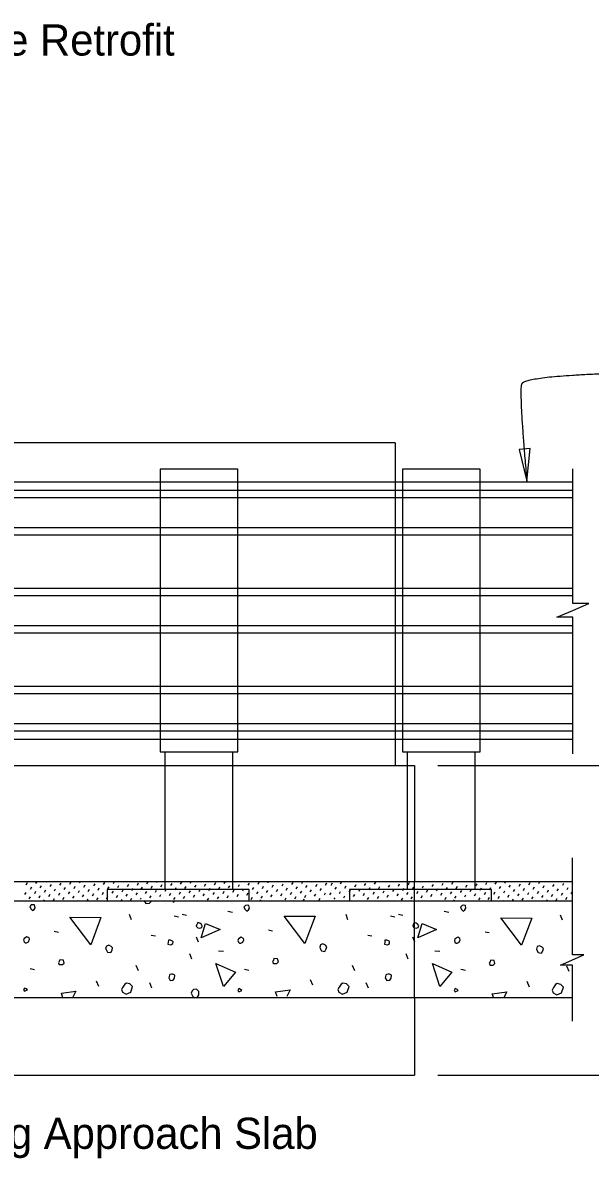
# Model space of a CAD drawing. Extents: x 1.5 to 68.7, y 0 to 31.1.
# Drawn here: x 34.15 to 37.81, y 9.2 to 16.53 of the extents above; entities that cross this region are included whole.
import ezdxf

# ---------------------------------------------------------------- set-up
doc = ezdxf.new("R2010")
doc.units = 0
for name, color, linetype in [('Dimension', 7, 'Continuous'), ('Miscellaneous', 7, 'Continuous'), ('TextStructures', 7, 'Continuous'), ('TrafBarrierConc', 7, 'Continuous')]:
    doc.layers.add(name, color=color, linetype=linetype)

msp = doc.modelspace()

# ---------------------------------------------------------------- linework, layer by layer
at = {"layer": 'Dimension'}
for p, q in [((36.8263, 11.7345), (39.8006, 11.7345)), ((36.8263, 9.7345), (39.8006, 9.7345))]:
    msp.add_line(p, q, dxfattribs=at)
msp.add_lwpolyline([(37.4003, 13.5697), (37.4212, 13.7799), (37.3508, 13.775)], close=True, dxfattribs=at)
for points in [[(37.6978, 11.8101), (37.6978, 12.6907), (37.5945, 12.6907), (37.6978, 12.7357), (37.8012, 12.7807), (37.6978, 12.7807), (37.6978, 13.649)], [(37.6953, 10.0834), (37.6953, 10.4448), (37.6178, 10.4448), (37.7678, 10.5111), (37.6953, 10.5111), (37.6953, 11.1369)]]:
    msp.add_lwpolyline(points, dxfattribs=at)
msp.add_open_spline([(37.8896, 14.2621), (37.3828, 14.2426), (37.3496, 14.1481), (37.4003, 13.5697)], degree=2, dxfattribs=at)
at = {"layer": 'Miscellaneous'}
for p, q in [((28.9195, 13.5645), (37.6978, 13.5645)), ((29.5771, 13.5123), (37.6978, 13.5123)), ((29.5783, 13.4641), (37.6978, 13.4641)), ((29.5831, 13.2713), (37.6978, 13.2713)), ((29.5842, 13.2231), (37.6978, 13.2231)), ((29.5807, 12.8791), (37.6978, 12.8791)), ((29.5795, 12.8309), (37.6978, 12.8309)), ((29.5747, 12.6381), (37.6978, 12.6381)), ((29.5735, 12.5899), (37.6978, 12.5899)), ((29.5831, 12.1978), (37.6978, 12.1978)), ((29.5842, 12.246), (37.6978, 12.246)), ((29.5771, 11.9567), (37.6978, 11.9567)), ((29.5783, 12.0049), (37.6978, 12.0049)), ((28.9195, 11.9044), (37.6978, 11.9044)), ((35.0654, 10.9324), (35.0654, 11.8211)), ((35.5029, 10.9324), (35.5029, 11.8211)), ((36.6296, 10.9324), (36.6296, 11.8211)), ((37.0671, 10.9324), (37.0671, 11.8211)), ((34.1686, 10.9633), (34.1767, 10.9773)), ((34.1963, 10.9356), (34.2044, 10.9496)), ((34.2321, 10.9714), (34.2397, 10.9845)), ((34.2598, 10.9437), (34.2679, 10.9577)), ((34.2875, 10.916), (34.2956, 10.93)), ((34.2956, 10.9795), (34.2985, 10.9845)), ((34.3233, 10.9518), (34.3314, 10.9658)), ((34.351, 10.9241), (34.3591, 10.9381)), ((34.3868, 10.9599), (34.3949, 10.9739)), ((34.4145, 10.9322), (34.4226, 10.9462)), ((34.4503, 10.968), (34.4584, 10.982)), ((34.478, 10.9403), (34.4861, 10.9543)), ((34.5057, 10.9126), (34.5138, 10.9266)), ((34.5138, 10.9761), (34.5186, 10.9845)), ((34.5415, 10.9484), (34.5496, 10.9624)), ((34.5692, 10.9207), (34.5773, 10.9347)), ((34.5773, 10.9842), (34.5774, 10.9845)), ((34.605, 10.9565), (34.6131, 10.9705)), ((34.6327, 10.9288), (34.6408, 10.9428)), ((34.6685, 10.9646), (34.6766, 10.9786)), ((34.6962, 10.9369), (34.7043, 10.9509)), ((34.732, 10.9727), (34.7388, 10.9845)), ((34.7597, 10.9451), (34.7678, 10.959)), ((34.7874, 10.9174), (34.7955, 10.9314)), ((34.7955, 10.9808), (34.7976, 10.9845)), ((34.8232, 10.9532), (34.8313, 10.9671)), ((34.8509, 10.9255), (34.859, 10.9395)), ((34.8867, 10.9613), (34.8948, 10.9753)), ((34.9118, 10.9343), (34.9199, 10.9483)), ((34.9476, 10.9701), (34.9557, 10.9841)), ((34.9753, 10.9424), (34.9834, 10.9564)), ((35.003, 10.9147), (35.0111, 10.9287)), ((35.0111, 10.9782), (35.0147, 10.9845)), ((35.0388, 10.9505), (35.0469, 10.9645)), ((35.0664, 10.9228), (35.0745, 10.9368)), ((35.1022, 10.9586), (35.1103, 10.9726)), ((35.1299, 10.9309), (35.138, 10.9449)), ((35.1657, 10.9667), (35.1738, 10.9807)), ((35.1934, 10.939), (35.2015, 10.953)), ((35.2292, 10.9748), (35.2348, 10.9845)), ((35.2569, 10.9471), (35.265, 10.9611)), ((35.2846, 10.9194), (35.2927, 10.9334)), ((35.2927, 10.9829), (35.2936, 10.9845)), ((35.3204, 10.9552), (35.3285, 10.9692)), ((35.3481, 10.9275), (35.3562, 10.9415)), ((35.3839, 10.9633), (35.392, 10.9773)), ((35.4116, 10.9356), (35.4197, 10.9496)), ((35.4474, 10.9714), (35.455, 10.9845)), ((35.4751, 10.9437), (35.4832, 10.9577)), ((35.5028, 10.916), (35.5109, 10.93)), ((35.5109, 10.9795), (35.5138, 10.9845)), ((35.5386, 10.9518), (35.5467, 10.9658)), ((35.5663, 10.9241), (35.5744, 10.9381)), ((35.6021, 10.9599), (35.6102, 10.9739)), ((35.6298, 10.9322), (35.6379, 10.9462)), ((35.6656, 10.968), (35.6737, 10.982)), ((35.6933, 10.9403), (35.7014, 10.9543)), ((35.721, 10.9126), (35.7291, 10.9266)), ((35.7291, 10.9761), (35.7339, 10.9845)), ((35.7568, 10.9484), (35.7649, 10.9624)), ((35.7845, 10.9207), (35.7926, 10.9347)), ((35.7926, 10.9842), (35.7927, 10.9845)), ((35.8203, 10.9565), (35.8284, 10.9705)), ((35.8479, 10.9288), (35.856, 10.9428)), ((35.8837, 10.9646), (35.8918, 10.9786)), ((35.9114, 10.9369), (35.9195, 10.9509)), ((35.9472, 10.9727), (35.954, 10.9845)), ((35.9749, 10.9451), (35.983, 10.959)), ((36.0026, 10.9174), (36.0107, 10.9314)), ((36.0107, 10.9808), (36.0128, 10.9845)), ((36.0384, 10.9532), (36.0465, 10.9671)), ((36.0661, 10.9255), (36.0742, 10.9395)), ((36.1019, 10.9613), (36.11, 10.9753)), ((36.1377, 10.9613), (36.1458, 10.9753)), ((36.1628, 10.9343), (36.1709, 10.9483)), ((36.1986, 10.9701), (36.2067, 10.9841)), ((36.2263, 10.9424), (36.2344, 10.9564)), ((36.254, 10.9147), (36.2621, 10.9287)), ((36.2898, 10.9505), (36.2979, 10.9645)), ((36.3175, 10.9228), (36.3256, 10.9368)), ((36.3533, 10.9586), (36.3614, 10.9726)), ((36.381, 10.9309), (36.3891, 10.9449)), ((36.4168, 10.9667), (36.4249, 10.9807)), ((36.4444, 10.939), (36.4526, 10.953)), ((36.5079, 10.9471), (36.516, 10.9611)), ((36.5356, 10.9194), (36.5437, 10.9334)), ((36.5714, 10.9552), (36.5795, 10.9692)), ((36.5991, 10.9275), (36.6072, 10.9415)), ((36.6349, 10.9633), (36.643, 10.9773)), ((36.6626, 10.9356), (36.6707, 10.9496)), ((36.7261, 10.9437), (36.7342, 10.9577)), ((36.7538, 10.916), (36.7619, 10.93)), ((36.7896, 10.9518), (36.7977, 10.9658)), ((36.8173, 10.9241), (36.8254, 10.9381)), ((36.8531, 10.9599), (36.8612, 10.9739)), ((36.8808, 10.9322), (36.8889, 10.9462)), ((36.9166, 10.968), (36.9247, 10.982)), ((36.9443, 10.9403), (36.9524, 10.9543)), ((36.972, 10.9126), (36.9801, 10.9266)), ((37.0078, 10.9484), (37.0159, 10.9624)), ((37.0355, 10.9207), (37.0436, 10.9347)), ((37.0713, 10.9565), (37.0794, 10.9705)), ((37.099, 10.9288), (37.1071, 10.9428)), ((37.1348, 10.9646), (37.1429, 10.9786)), ((37.16, 10.931), (37.1681, 10.945)), ((37.1958, 10.9668), (37.2039, 10.9808)), ((37.2235, 10.9391), (37.2316, 10.9531)), ((37.2593, 10.9749), (37.2649, 10.9845)), ((37.287, 10.9472), (37.2951, 10.9612)), ((37.3147, 10.9195), (37.3228, 10.9335)), ((37.3228, 10.983), (37.3237, 10.9845)), ((37.3505, 10.9553), (37.3586, 10.9693)), ((37.3782, 10.9276), (37.3863, 10.9416)), ((37.414, 10.9634), (37.4221, 10.9774)), ((37.4417, 10.9357), (37.4498, 10.9497)), ((37.4775, 10.9715), (37.485, 10.9845)), ((37.5052, 10.9438), (37.5133, 10.9578)), ((37.5329, 10.9161), (37.541, 10.9301)), ((37.541, 10.9796), (37.5438, 10.9845)), ((37.5687, 10.9519), (37.5768, 10.9659)), ((37.5964, 10.9242), (37.6045, 10.9382)), ((37.6322, 10.96), (37.6403, 10.974)), ((37.6599, 10.9323), (37.668, 10.9463)), ((37.6956, 10.9681), (37.6978, 10.9718)), ((34.1605, 10.8998), (34.1686, 10.9138)), ((34.1882, 10.8721), (34.1963, 10.8861)), ((34.224, 10.9079), (34.2321, 10.9219)), ((34.2517, 10.8802), (34.2598, 10.8942)), ((34.2834, 10.8595), (34.2875, 10.8665)), ((34.3152, 10.8883), (34.3233, 10.9023)), ((34.3429, 10.8606), (34.351, 10.8746)), ((34.3787, 10.8964), (34.3868, 10.9104)), ((34.4064, 10.8687), (34.4145, 10.8827)), ((34.4422, 10.9045), (34.4503, 10.9185)), ((34.4699, 10.8768), (34.478, 10.8908)), ((34.5036, 10.8595), (34.5057, 10.8631)), ((34.5334, 10.8849), (34.5415, 10.8989)), ((34.5624, 10.8595), (34.5692, 10.8712)), ((34.5969, 10.893), (34.605, 10.907)), ((34.6246, 10.8654), (34.6327, 10.8793)), ((34.6604, 10.9012), (34.6685, 10.9151)), ((34.6881, 10.8735), (34.6962, 10.8875)), ((34.7237, 10.8595), (34.7239, 10.8598)), ((34.7239, 10.9093), (34.732, 10.9232)), ((34.7516, 10.8816), (34.7597, 10.8956)), ((34.7825, 10.8595), (34.7874, 10.8679)), ((34.8151, 10.8897), (34.8232, 10.9037)), ((34.8428, 10.862), (34.8509, 10.876)), ((34.8786, 10.8978), (34.8867, 10.9118)), ((34.9062, 10.8701), (34.9113, 10.8788)), ((34.9395, 10.9066), (34.9476, 10.9206)), ((34.9672, 10.8789), (34.9753, 10.8929)), ((35.0306, 10.887), (35.0388, 10.901)), ((35.0941, 10.8951), (35.1022, 10.9091)), ((35.1218, 10.8674), (35.1299, 10.8814)), ((35.1576, 10.9032), (35.1657, 10.9172)), ((35.1853, 10.8755), (35.1934, 10.8895)), ((35.2211, 10.9113), (35.2292, 10.9253)), ((35.2488, 10.8836), (35.2569, 10.8976)), ((35.3123, 10.8917), (35.3204, 10.9057)), ((35.34, 10.864), (35.3481, 10.878)), ((35.3758, 10.8998), (35.3839, 10.9138)), ((35.3996, 10.8595), (35.4009, 10.8618)), ((35.4035, 10.8721), (35.4116, 10.8861)), ((35.4393, 10.9079), (35.4474, 10.9219)), ((35.467, 10.8802), (35.4751, 10.8942)), ((35.5305, 10.8883), (35.5386, 10.9023)), ((35.594, 10.8964), (35.6021, 10.9104)), ((35.6217, 10.8687), (35.6298, 10.8827)), ((35.6575, 10.9045), (35.6656, 10.9185)), ((35.6785, 10.8595), (35.6826, 10.8665)), ((35.6852, 10.8768), (35.6933, 10.8908)), ((35.7487, 10.8849), (35.7568, 10.8989)), ((35.8121, 10.893), (35.8203, 10.907)), ((35.8398, 10.8654), (35.8479, 10.8793)), ((35.8756, 10.9012), (35.8837, 10.9151)), ((35.8986, 10.8595), (35.9008, 10.8631)), ((35.9033, 10.8735), (35.9114, 10.8875)), ((35.9391, 10.9093), (35.9472, 10.9232)), ((35.9574, 10.8595), (35.9643, 10.8712)), ((35.9668, 10.8816), (35.9749, 10.8956)), ((36.0303, 10.8897), (36.0384, 10.9037)), ((36.058, 10.862), (36.0661, 10.876)), ((36.0938, 10.8978), (36.1019, 10.9118)), ((36.1296, 10.8978), (36.1377, 10.9118)), ((36.1573, 10.8701), (36.1623, 10.8788)), ((36.1905, 10.9066), (36.1986, 10.9206)), ((36.2182, 10.8789), (36.2263, 10.8929)), ((36.2817, 10.887), (36.2898, 10.901)), ((36.3452, 10.8951), (36.3533, 10.9091)), ((36.3729, 10.8674), (36.381, 10.8814)), ((36.4087, 10.9032), (36.4168, 10.9172)), ((36.4363, 10.8755), (36.4444, 10.8895)), ((36.4721, 10.9113), (36.4802, 10.9253)), ((36.4998, 10.8836), (36.5079, 10.8976)), ((36.5633, 10.8917), (36.5714, 10.9057)), ((36.591, 10.864), (36.5991, 10.878)), ((36.6268, 10.8998), (36.6349, 10.9138)), ((36.6506, 10.8595), (36.6519, 10.8618)), ((36.6545, 10.8721), (36.6626, 10.8861)), ((36.6903, 10.9079), (36.6984, 10.9219)), ((36.718, 10.8802), (36.7261, 10.8942)), ((36.7815, 10.8883), (36.7896, 10.9023)), ((36.845, 10.8964), (36.8531, 10.9104)), ((36.8727, 10.8687), (36.8808, 10.8827)), ((36.9085, 10.9045), (36.9166, 10.9185)), ((36.9295, 10.8595), (36.9336, 10.8665)), ((36.9362, 10.8768), (36.9443, 10.8908)), ((36.9997, 10.8849), (37.0078, 10.8989)), ((37.0632, 10.893), (37.0713, 10.907)), ((37.0909, 10.8654), (37.099, 10.8793)), ((37.1267, 10.9012), (37.1348, 10.9151)), ((37.1519, 10.8675), (37.16, 10.8815)), ((37.1877, 10.9033), (37.1958, 10.9173)), ((37.2154, 10.8756), (37.2235, 10.8896)), ((37.2499, 10.8595), (37.2512, 10.8619)), ((37.2512, 10.9114), (37.2593, 10.9254)), ((37.2789, 10.8837), (37.287, 10.8977)), ((37.3087, 10.8595), (37.3147, 10.87)), ((37.3424, 10.8918), (37.3505, 10.9058)), ((37.3701, 10.8641), (37.3782, 10.8781)), ((37.4059, 10.8999), (37.414, 10.9139)), ((37.4336, 10.8722), (37.4417, 10.8862)), ((37.4694, 10.908), (37.4775, 10.922)), ((37.4971, 10.8803), (37.5052, 10.8943)), ((37.5044, 10.8561), (37.5045, 10.8563)), ((37.5288, 10.8595), (37.5329, 10.8666)), ((37.5606, 10.8884), (37.5687, 10.9024)), ((37.5883, 10.8607), (37.5964, 10.8747)), ((37.6241, 10.8965), (37.6322, 10.9105)), ((37.6517, 10.8688), (37.6599, 10.8828)), ((37.6875, 10.9046), (37.6956, 10.9186)), ((35.4704, 10.7923), (35.5004, 10.787)), ((36.8675, 10.7923), (36.8975, 10.787)), ((34.849, 10.7375), (34.8366, 10.7711)), ((35.123, 10.764), (35.1513, 10.757)), ((35.1747, 10.7733), (35.203, 10.7662)), ((36.2461, 10.7375), (36.2337, 10.7711)), ((36.5201, 10.764), (36.5484, 10.757)), ((36.5718, 10.7733), (36.6001, 10.7662)), ((37.6297, 10.7341), (37.6173, 10.7677)), ((34.3505, 10.6633), (34.377, 10.658)), ((34.9763, 10.6385), (35.0028, 10.6332)), ((35.7329, 10.6715), (35.7594, 10.6662)), ((36.3734, 10.6385), (36.3999, 10.6332)), ((37.1312, 10.6598), (37.1577, 10.6545)), ((35.2808, 10.5921), (35.2684, 10.6257)), ((36.6779, 10.5921), (36.6655, 10.6257)), ((35.2384, 10.4825), (35.2242, 10.5179)), ((35.4103, 10.5378), (35.4421, 10.5342)), ((36.6355, 10.4825), (36.6213, 10.5179)), ((36.8074, 10.5378), (36.8392, 10.5342)), ((34.1949, 10.4229), (34.2232, 10.4158)), ((34.8932, 10.4069), (34.8791, 10.4423)), ((35.5782, 10.4193), (35.6065, 10.4122)), ((36.2903, 10.4069), (36.2762, 10.4423)), ((36.9753, 10.4193), (37.0036, 10.4122)), ((37.6739, 10.4035), (37.6597, 10.4389)), ((34.6369, 10.3062), (34.6227, 10.3415)), ((36.0192, 10.3144), (36.0051, 10.3497)), ((34.9803, 10.2951), (34.9661, 10.3305)), ((36.3774, 10.2951), (36.3632, 10.3305)), ((37.4176, 10.3027), (37.4034, 10.3381))]:
    msp.add_line(p, q, dxfattribs=at)
for points in [[(35.0342, 11.8211), (35.5342, 11.8211), (35.5342, 13.6478), (35.0342, 13.6478)], [(36.5984, 11.8211), (37.0984, 11.8211), (37.0984, 13.6478), (36.5984, 13.6478)], [(34.6907, 10.8595), (35.6073, 10.8595), (35.6073, 10.9324), (34.6907, 10.9324)], [(36.255, 10.8595), (37.1716, 10.8595), (37.1716, 10.9324), (36.255, 10.9324)]]:
    msp.add_lwpolyline(points, close=True, dxfattribs=at)
for points in [[(34.9311, 10.8594), (34.9409, 10.8436), (34.9639, 10.8453), (34.9728, 10.8542), (34.978, 10.8594)], [(35.1199, 10.8493), (35.1167, 10.8594)], [(35.1251, 10.8594), (35.1199, 10.8493)], [(34.1985, 10.8082), (34.2091, 10.7976), (34.2197, 10.8047), (34.2268, 10.8153), (34.2232, 10.833), (34.2144, 10.8347), (34.202, 10.833), (34.1914, 10.8224), (34.1985, 10.8082)], [(35.5818, 10.8047), (35.5924, 10.7941), (35.603, 10.8012), (35.61, 10.8118), (35.6065, 10.8294), (35.5977, 10.8312), (35.5853, 10.8294), (35.5747, 10.8188), (35.5818, 10.8047)], [(36.9788, 10.8047), (36.9894, 10.7941), (37.0001, 10.8012), (37.0071, 10.8118), (37.0036, 10.8294), (36.9948, 10.8312), (36.9824, 10.8294), (36.9718, 10.8188), (36.9788, 10.8047)], [(34.5856, 10.5766), (34.4513, 10.7534), (34.651, 10.7517), (34.5856, 10.5766)], [(35.2773, 10.6849), (35.2896, 10.6832), (35.302, 10.6885), (35.3055, 10.6991), (35.3002, 10.7079), (35.2896, 10.715), (35.2773, 10.7203), (35.2702, 10.7061), (35.2667, 10.6955), (35.2773, 10.6849)], [(35.2989, 10.6208), (35.3272, 10.7128), (35.4209, 10.6756), (35.2989, 10.6208)], [(35.968, 10.5849), (35.8336, 10.7616), (36.0334, 10.7599), (35.968, 10.5849)], [(36.6743, 10.6849), (36.6867, 10.6832), (36.6991, 10.6885), (36.7026, 10.6991), (36.6973, 10.7079), (36.6867, 10.715), (36.6743, 10.7203), (36.6673, 10.7061), (36.6637, 10.6955), (36.6743, 10.6849)], [(36.696, 10.6208), (36.7243, 10.7128), (36.818, 10.6756), (36.696, 10.6208)], [(37.3663, 10.5732), (37.2319, 10.75), (37.4317, 10.7482), (37.3663, 10.5732)], [(34.1631, 10.589), (34.1702, 10.589), (34.1843, 10.5961), (34.1896, 10.612), (34.1879, 10.6208), (34.1737, 10.6279), (34.1561, 10.6173), (34.1525, 10.6067), (34.1561, 10.5961), (34.1631, 10.589)], [(34.6846, 10.5448), (34.6935, 10.5289), (34.7147, 10.5254), (34.7235, 10.5413), (34.727, 10.5554), (34.7182, 10.5643), (34.7023, 10.5731), (34.6864, 10.5678), (34.6811, 10.5519), (34.6846, 10.5448)], [(35.0841, 10.5802), (35.1036, 10.5749), (35.116, 10.5837), (35.1177, 10.5961), (35.1142, 10.5996), (35.1, 10.6067), (35.0877, 10.6049), (35.0859, 10.5926), (35.0841, 10.5802)], [(35.5464, 10.5855), (35.5535, 10.5855), (35.5676, 10.5926), (35.5729, 10.6085), (35.5712, 10.6173), (35.557, 10.6244), (35.5393, 10.6138), (35.5358, 10.6032), (35.5393, 10.5926), (35.5464, 10.5855)], [(36.067, 10.553), (36.0758, 10.5371), (36.097, 10.5336), (36.1059, 10.5495), (36.1094, 10.5636), (36.1006, 10.5725), (36.0847, 10.5813), (36.0687, 10.576), (36.0634, 10.5601), (36.067, 10.553)], [(36.4812, 10.5802), (36.5007, 10.5749), (36.513, 10.5837), (36.5148, 10.5961), (36.5113, 10.5996), (36.4971, 10.6067), (36.4848, 10.6049), (36.483, 10.5926), (36.4812, 10.5802)], [(36.9435, 10.5855), (36.9506, 10.5855), (36.9647, 10.5926), (36.97, 10.6085), (36.9682, 10.6173), (36.9541, 10.6244), (36.9364, 10.6138), (36.9329, 10.6032), (36.9364, 10.5926), (36.9435, 10.5855)], [(37.4653, 10.5414), (37.4741, 10.5255), (37.4953, 10.5219), (37.5042, 10.5379), (37.5077, 10.552), (37.4989, 10.5608), (37.483, 10.5697), (37.4671, 10.5644), (37.4618, 10.5485), (37.4653, 10.5414)], [(35.7647, 10.4558), (35.7859, 10.4558), (35.7965, 10.4664), (35.7912, 10.4859), (35.7682, 10.4876), (35.7647, 10.477), (35.7594, 10.4682), (35.7647, 10.4558), (35.7612, 10.4593)], [(34.3823, 10.4476), (34.4035, 10.4476), (34.4141, 10.4582), (34.4088, 10.4777), (34.3859, 10.4794), (34.3823, 10.4688), (34.377, 10.46), (34.3823, 10.4476), (34.3788, 10.4511)], [(35.4417, 10.3075), (35.3939, 10.4542), (35.5194, 10.3994), (35.4417, 10.3075)], [(36.8387, 10.3075), (36.791, 10.4542), (36.9165, 10.3994), (36.8387, 10.3075)], [(37.163, 10.4442), (37.1842, 10.4442), (37.1948, 10.4548), (37.1895, 10.4742), (37.1665, 10.476), (37.163, 10.4654), (37.1577, 10.4565), (37.163, 10.4442), (37.1595, 10.4477)], [(35.0899, 10.3623), (35.0987, 10.3464), (35.1182, 10.3482), (35.127, 10.3605), (35.1288, 10.38), (35.1164, 10.3853), (35.1076, 10.3871), (35.0969, 10.3835), (35.0934, 10.38), (35.0899, 10.3623)], [(36.487, 10.3623), (36.4958, 10.3464), (36.5152, 10.3482), (36.5241, 10.3605), (36.5259, 10.38), (36.5135, 10.3853), (36.5046, 10.3871), (36.494, 10.3835), (36.4905, 10.38), (36.487, 10.3623)], [(34.1574, 10.2757), (34.1768, 10.2845), (34.1698, 10.2916), (34.1574, 10.2969), (34.1521, 10.2845), (34.1574, 10.2757)], [(34.4059, 10.2344), (34.3965, 10.2638), (34.4902, 10.2761), (34.4687, 10.2344)], [(34.7907, 10.2691), (34.8137, 10.2567), (34.8437, 10.2691), (34.8561, 10.3062), (34.8384, 10.3239), (34.8154, 10.3292), (34.8048, 10.3221), (34.7924, 10.3026), (34.7836, 10.2867), (34.7907, 10.2691)], [(35.2671, 10.2344), (35.2773, 10.2421), (35.2843, 10.2527), (35.2843, 10.2739), (35.2684, 10.2898), (35.249, 10.2881), (35.2401, 10.2792), (35.2348, 10.2633)], [(35.5407, 10.2721), (35.5601, 10.281), (35.553, 10.2881), (35.5407, 10.2934), (35.5354, 10.281), (35.5407, 10.2721)], [(35.7883, 10.2427), (35.7788, 10.272), (35.8725, 10.2843), (35.851, 10.2427)], [(36.1878, 10.2691), (36.2107, 10.2567), (36.2408, 10.2691), (36.2532, 10.3062), (36.2355, 10.3239), (36.2125, 10.3292), (36.2019, 10.3221), (36.1895, 10.3026), (36.1807, 10.2867), (36.1878, 10.2691)], [(36.9377, 10.2721), (36.9572, 10.281), (36.9501, 10.2881), (36.9377, 10.2934), (36.9324, 10.281), (36.9377, 10.2721)], [(37.1866, 10.231), (37.1771, 10.2603), (37.2708, 10.2727), (37.2494, 10.231)], [(37.5714, 10.2656), (37.5943, 10.2532), (37.6244, 10.2656), (37.6368, 10.3027), (37.6191, 10.3204), (37.5961, 10.3257), (37.5855, 10.3187), (37.5731, 10.2992), (37.5643, 10.2833), (37.5714, 10.2656)], [(35.2348, 10.2633), (35.2454, 10.2421), (35.2582, 10.2344)]]:
    msp.add_lwpolyline(points, dxfattribs=at)
at = {"layer": 'TrafBarrierConc'}
for p, q in [((36.5515, 13.8178), (26.2771, 13.8178)), ((36.5515, 13.8178), (36.5515, 11.7345)), ((26.2771, 11.7345), (36.6763, 11.7345)), ((36.5515, 11.7345), (36.6763, 11.7345)), ((36.6763, 11.7345), (36.6763, 10.9845)), ((27.4971, 10.9845), (37.6978, 10.9845)), ((36.6763, 10.2345), (36.6763, 10.9845)), ((28.2772, 10.8595), (34.2217, 10.8595)), ((34.2217, 10.8595), (37.6978, 10.8595)), ((31.4971, 10.2345), (37.6978, 10.2345)), ((36.6763, 10.2345), (36.6763, 9.7345)), ((27.4971, 9.7345), (36.6763, 9.7345))]:
    msp.add_line(p, q, dxfattribs=at)

# ---------------------------------------------------------------- texts
at = {"layer": 'Dimension'}
msp.add_text('Parallel Portion of Vertical Face Retrofit ', height=0.2016, dxfattribs=at).set_placement((30.4075, 16.3181))
at = {"layer": 'TextStructures'}
msp.add_text('Existing Approach Slab', height=0.2016, dxfattribs=at).set_placement((33.2635, 9.2581))

doc.saveas('drawing.dxf')
